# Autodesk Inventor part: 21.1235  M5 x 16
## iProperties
Created: 2006-02
Part Number: 21.1235  M5 x 16
Material: Steel, Mild
Description: Cylinder Head Cap Screw
Document SubType Name: Modeling
Standard: DIN 7984
Designer: Andy Moles
Standards Organization: DIN
Language: en-US
Size Designation: M5 x 16
Categories: <MemberInstance><Categories><Category DisplayName="Fasteners" InternalName="e4da775c-781d-43d5-af7c-5136215cf5a6" Mnemonic="FSTN"><Category DisplayName="Bolts"
Density: 7.86 g/cm^3
Mass: 3.81606 g
Surface Area: 4.77789 cm^2
Volume: 0.485504 cm^3
Author: Andy Moles
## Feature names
1. Body [Revolution]
2. Slot [Extrusion]
3. Fillet1
4. Chamfer1
